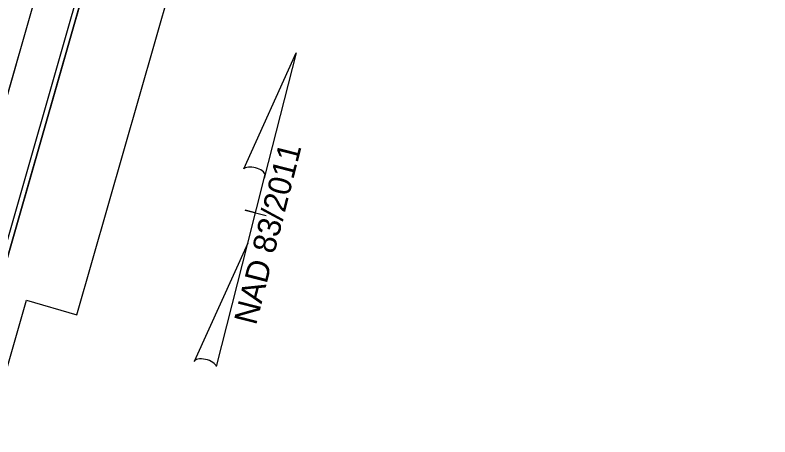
# Model space of a CAD drawing. Extents: x 2096976 to 2098492, y 681809 to 689636.
# Drawn here: x 2097354.7 to 2097733.7, y 689155.8 to 689367.6 of the extents above; entities that cross this region are included whole.
import ezdxf

# ---------------------------------------------------------------- set-up
doc = ezdxf.new("R2010")
doc.units = 0
for name, color, linetype in [('Prop North Arrow NAD83 for Plan Sheets CELL', 7, 'Continuous'), ('Scratch_Level_6', 7, 'Continuous'), ('Sheet Cutting Line CELL', 7, 'Continuous'), ('Sheet Plan CELL', 7, 'Continuous'), ('Sheet Plot Border Inside CELL', 7, 'Continuous'), ('Sheet Plot Border Outside CELL', 7, 'Continuous')]:
    doc.layers.add(name, color=color, linetype=linetype)

msp = doc.modelspace()

# ---------------------------------------------------------------- linework, layer by layer
at = {"layer": 'Prop North Arrow NAD83 for Plan Sheets CELL'}
for p, q in [((2097469.5, 689290.42), (2097495.84, 689348.66)), ((2097495.91, 689348.64), (2097479.87, 689285.74)), ((2097471.54, 689253.11), (2097480.34, 689287.58)), ((2097479.87, 689285.74), (2097480.32, 689287.52)), ((2097474.84, 689268.52), (2097470.17, 689269.71)), ((2097470.24, 689269.7), (2097480.76, 689267.01)), ((2097471.54, 689253.11), (2097444.69, 689193.73)), ((2097455.81, 689191.17), (2097471.54, 689253.11))]:
    msp.add_line(p, q, dxfattribs=at)
for centre, start_param, end_param in [((2097474.77, 689288.38), 0.216388, 2.908219), ((2097450.21, 689192.09), 0.201328, 3.141593)]:
    msp.add_ellipse(centre, major_axis=(5.56, -1.46), ratio=0.461098, start_param=start_param, end_param=end_param, dxfattribs=at)
at = {"layer": 'Scratch_Level_6'}
msp.add_lwpolyline([(2098102.1, 688055.1), (2097347.73, 688084.03), (2097057.83, 688167.01), (2097360.53, 689224.43), (2097385.77, 689217.21), (2097440.82, 689409.53), (2097570.41, 689372.44), (2097625.46, 689564.76), (2098465.42, 689324.31)], close=True, dxfattribs=at)
at = {"layer": 'Sheet Cutting Line CELL'}
msp.add_line((2097439.02, 689635.81), (2096975.72, 688017.32), dxfattribs=at)
at = {"layer": 'Sheet Plan CELL'}
for points in [[(2097455.97, 689613.3), (2097043.16, 688171.19), (2098052.61, 687882.22), (2098465.42, 689324.31)], [(2098052.61, 687882.22), (2097043.17, 688171.15), (2097400.9, 689420.95), (2097545.17, 689379.67), (2097600.23, 689571.98), (2098465.42, 689324.31)]]:
    msp.add_lwpolyline(points, close=True, dxfattribs=at)
at = {"layer": 'Sheet Plot Border Inside CELL'}
msp.add_lwpolyline([(2098012.79, 687733.97), (2098471.26, 689335.63), (2097457.01, 689625.98), (2096998.53, 688024.31)], close=True, dxfattribs=at)
at = {"layer": 'Sheet Plot Border Outside CELL'}
msp.add_lwpolyline([(2098028.44, 687715.97), (2098491.74, 689334.46), (2097439.02, 689635.81), (2096975.72, 688017.32)], close=True, dxfattribs=at)

# ---------------------------------------------------------------- texts
at = {"layer": 'Prop North Arrow NAD83 for Plan Sheets CELL'}
msp.add_text('NAD 83/2011', height=11.5436, rotation=75.6911, dxfattribs=at).set_placement((2097475.69, 689211.58))

doc.saveas('drawing.dxf')
